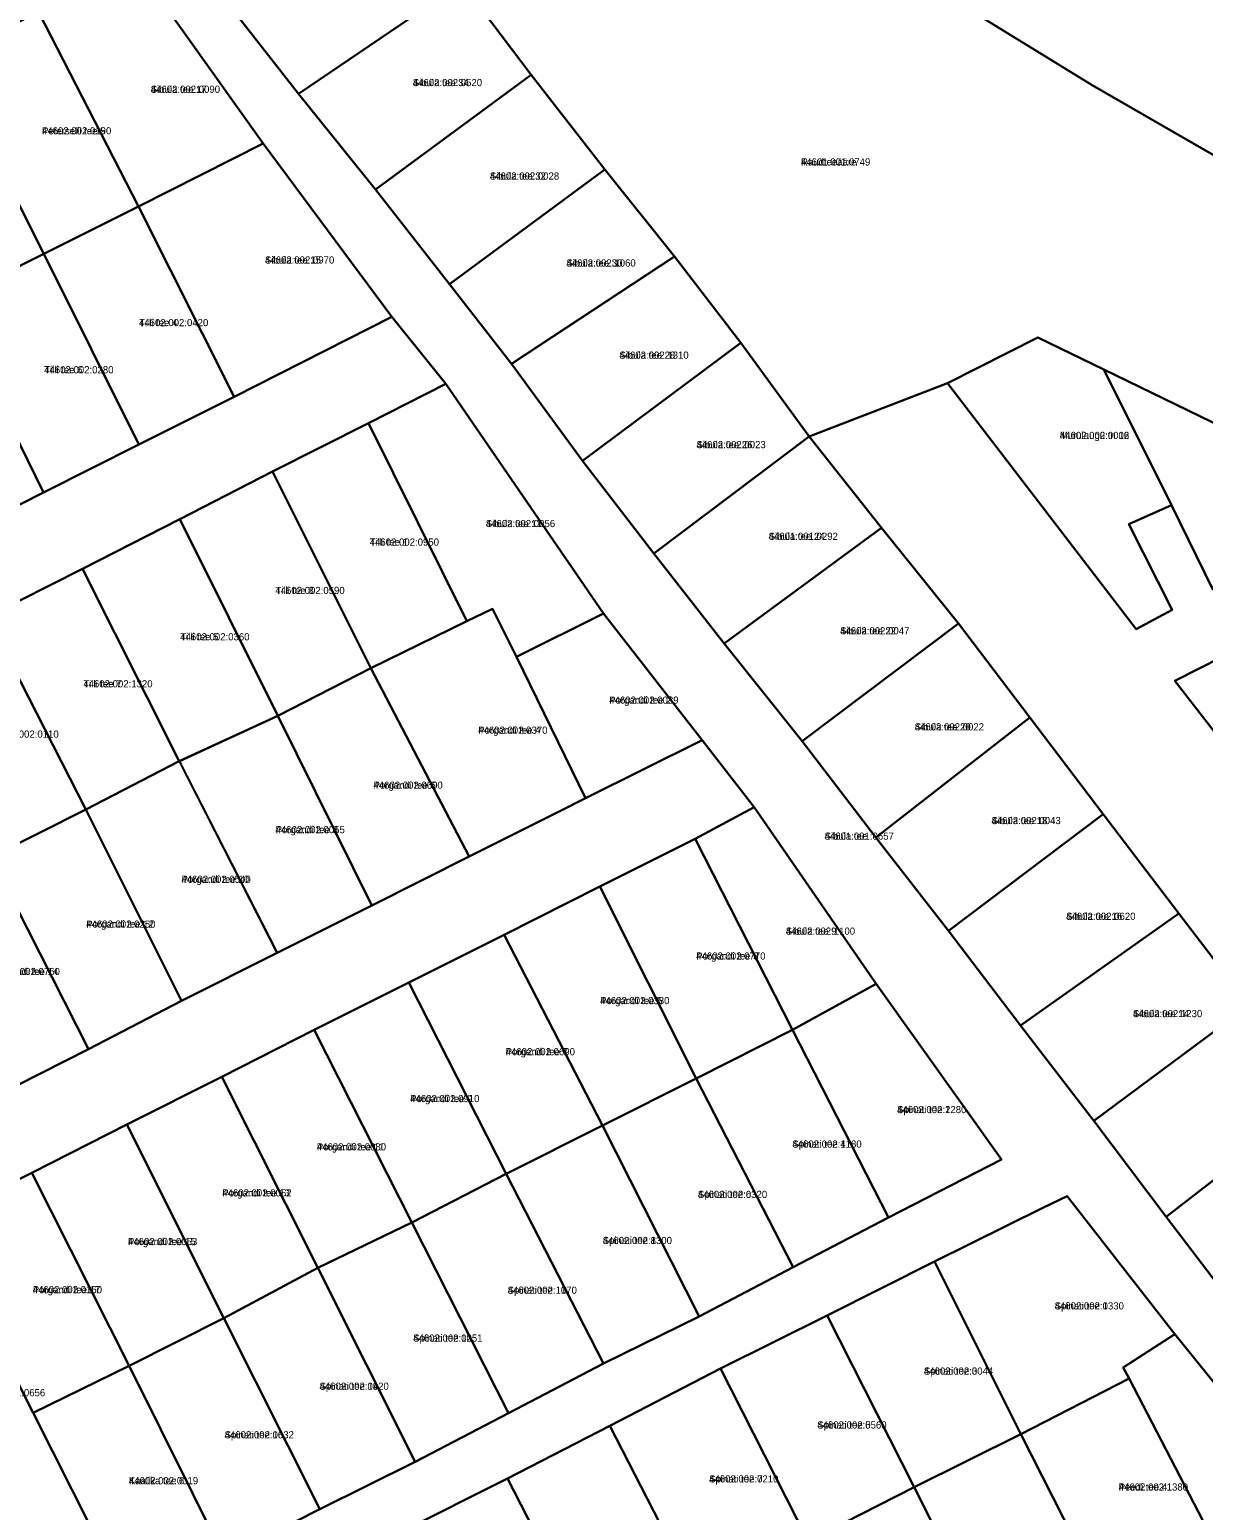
# Model space of a CAD drawing. Extents: x 551843 to 558501, y 6589003 to 6595718.
# Drawn here: x 554896.4 to 555142, y 6592596.3 to 6592906.2 of the extents above; entities that cross this region are included whole.
import ezdxf

# ---------------------------------------------------------------- set-up
doc = ezdxf.new("R2010")
doc.units = 0
for name, color, linetype in [('L_AADRESS', 7, 'Continuous'), ('PIIR', 7, 'Continuous'), ('TUNNUS', 7, 'Continuous')]:
    doc.layers.add(name, color=color, linetype=linetype)

msp = doc.modelspace()

# ---------------------------------------------------------------- linework, layer by layer
at = {"layer": 'PIIR'}
for points in [[(555357.71, 6592732.06), (555331.9, 6592760.71), (555302.6, 6592785.47), (555269.03, 6592807.67), (555235.4, 6592827.33), (555118.69, 6592894.62), (555044.93, 6592939.98), (555015.71, 6592961.33), (554988.11, 6592984.79), (554962.01, 6593010.23), (554937.73, 6593037.35), (554915.67, 6593065.87), (554895.44, 6593095.83), (554875.06, 6593131.38), (554857.59, 6593168.3), (554843.07, 6593206.48), (554831.62, 6593245.96)], [(554831.62, 6593245.96), (554843.07, 6593206.48), (554857.59, 6593168.3), (554875.06, 6593131.38), (554895.44, 6593095.83), (554915.67, 6593065.87), (554937.73, 6593037.35), (554962.01, 6593010.23), (554988.11, 6592984.79), (555015.71, 6592961.33), (555044.93, 6592939.98), (555118.69, 6592894.62), (555235.4, 6592827.33), (555269.03, 6592807.67), (555302.6, 6592785.47), (555331.9, 6592760.71), (555357.71, 6592732.06)], [(554937.17, 6592586.43), (554957.1, 6592596.52), (554977.01, 6592606.45), (554996.59, 6592616.65), (555016.42, 6592627.02), (555036.46, 6592636.84), (555056.16, 6592647.21), (555076.11, 6592657.57), (555099.74, 6592669.68), (555073.53, 6592706.46), (555047.96, 6592743.47), (555037.07, 6592757.5), (555016.41, 6592784.02), (554983.42, 6592832.06), (554972.12, 6592846.08), (554945.2, 6592882.4), (554918.38, 6592920.14)], [(555379.25, 6592709.61), (555333.63, 6592731.77), (555287.48, 6592754.21), (555235.64, 6592779.42), (555225.94, 6592784.13), (555194.48, 6592799.4), (555178.8, 6592807.05), (555121.11, 6592835.09), (555107.33, 6592841.78), (555088.39, 6592832.21), (555059.5, 6592821.07), (555045.19, 6592840.66), (555031.29, 6592858.7), (555016.73, 6592876.96), (555001.32, 6592896.74), (554986.83, 6592915.99)], [(554938.02, 6592911.42), (554952.61, 6592892.79), (554968.73, 6592872.78), (554984.2, 6592852.9), (554997.2, 6592836.28), (555012.03, 6592815.96), (555026.99, 6592796.53), (555041.71, 6592777.75), (555057.98, 6592757.31), (555073.44, 6592737.12), (555088.6, 6592717.61), (555103.7, 6592697.74), (555119.02, 6592677.8), (555134.21, 6592657.71), (555149.2, 6592638.05)], [(554879.63, 6592799.39), (554899.28, 6592809.31), (554919.22, 6592819.36), (554939.16, 6592829.38), (554972.12, 6592846.08), (554983.42, 6592832.06), (554967.24, 6592823.87), (554947.19, 6592813.73), (554927.78, 6592803.74), (554907.45, 6592793.36), (554887.5, 6592783.3)], [(555151.56, 6592701.94), (555136.8, 6592721.21), (555120.98, 6592742), (555105.63, 6592762.22), (555090.71, 6592781.94), (555074.62, 6592801.95), (555059.5, 6592821.07), (555088.39, 6592832.21), (555127.87, 6592780.7), (555135.46, 6592784.75), (555126.36, 6592802.68), (555135.28, 6592806.7), (555143.94, 6592789.01)], [(555171.08, 6592787.67), (555135.97, 6592769.94), (555153.13, 6592747.81)], [(554888.68, 6592682.72), (554908.65, 6592692.84), (554928.17, 6592702.94), (554948.16, 6592712.97), (554967.96, 6592722.91), (554988.33, 6592733.16), (555007.3, 6592742.64), (555012.67, 6592745.32), (555037.07, 6592757.5), (555047.96, 6592743.47), (555035.64, 6592736.84), (555015.66, 6592726.88), (554995.66, 6592716.72), (554975.72, 6592706.75), (554955.9, 6592696.86), (554936.57, 6592686.99), (554916.68, 6592677.03), (554896.85, 6592666.95), (554876.81, 6592656.9), (554897.07, 6592616.68), (554917.4, 6592576.46)], [(555162.2, 6592600.73), (555136.01, 6592633.16), (555113.48, 6592662.05), (555108.35, 6592659.6), (555085.68, 6592648.33), (555063.22, 6592637.04), (555040.93, 6592625.99), (555017.79, 6592613.99), (554996.34, 6592602.97), (554973.97, 6592591.72)]]:
    msp.add_lwpolyline(points, dxfattribs=at)
for points in [[(554952.61, 6592892.79), (554938.02, 6592911.42), (554971.51, 6592936.51), (554986.83, 6592915.99)], [(554919.11, 6592869.18), (554898.19, 6592909.95), (554918.38, 6592920.14), (554945.2, 6592882.4)], [(554968.73, 6592872.78), (554952.61, 6592892.79), (554986.83, 6592915.99), (555001.32, 6592896.74)], [(554899.34, 6592859.3), (554878.78, 6592900.13), (554898.19, 6592909.95), (554919.11, 6592869.18)], [(554858.94, 6592890.16), (554878.78, 6592900.13), (554899.34, 6592859.3), (554879.57, 6592849.36)], [(554968.73, 6592872.78), (555001.32, 6592896.74), (555016.73, 6592876.96), (554984.2, 6592852.9)], [(554945.2, 6592882.4), (554972.12, 6592846.08), (554939.16, 6592829.38), (554919.11, 6592869.18)], [(554997.2, 6592836.28), (554984.2, 6592852.9), (555016.73, 6592876.96), (555031.29, 6592858.7)], [(554919.11, 6592869.18), (554939.16, 6592829.38), (554919.22, 6592819.36), (554899.34, 6592859.3)], [(554879.59, 6592849.37), (554899.34, 6592859.3), (554919.22, 6592819.36), (554899.28, 6592809.31)], [(555012.03, 6592815.96), (554997.2, 6592836.28), (555031.29, 6592858.7), (555045.19, 6592840.66)], [(554879.59, 6592849.37), (554899.28, 6592809.31), (554879.63, 6592799.39), (554858.83, 6592839.26)], [(555045.19, 6592840.66), (555059.5, 6592821.07), (555026.99, 6592796.53), (555012.03, 6592815.96)], [(555088.39, 6592832.21), (555107.33, 6592841.78), (555121.11, 6592835.09), (555135.28, 6592806.7), (555126.36, 6592802.68), (555135.46, 6592784.75), (555127.87, 6592780.7)], [(555178.8, 6592807.05), (555143.94, 6592789.01), (555135.28, 6592806.7), (555121.11, 6592835.09)], [(554967.24, 6592823.87), (554983.42, 6592832.06), (555016.41, 6592784.02), (554998.21, 6592774.93), (554993.21, 6592785), (554987.84, 6592782.4)], [(554967.24, 6592823.87), (554987.84, 6592782.4), (554967.78, 6592772.56), (554947.19, 6592813.73)], [(555041.71, 6592777.75), (555026.99, 6592796.53), (555059.5, 6592821.07), (555074.62, 6592801.95)], [(554947.19, 6592813.73), (554967.78, 6592772.56), (554948.28, 6592762.6), (554927.78, 6592803.74)], [(554927.78, 6592803.74), (554948.28, 6592762.6), (554927.67, 6592753.11), (554907.45, 6592793.36)], [(555041.71, 6592777.75), (555074.62, 6592801.95), (555090.71, 6592781.94), (555057.98, 6592757.31)], [(554907.45, 6592793.36), (554927.67, 6592753.11), (554908.09, 6592742.97), (554887.5, 6592783.3)], [(554967.78, 6592772.56), (554987.84, 6592782.4), (554993.21, 6592785), (554998.21, 6592774.93), (555012.67, 6592745.32), (555007.3, 6592742.64), (554988.33, 6592733.16)], [(555178.6, 6592760.83), (555153.13, 6592747.81), (555135.97, 6592769.94), (555171.08, 6592787.67), (555183.36, 6592763.27)], [(554867.79, 6592773.85), (554887.5, 6592783.3), (554908.09, 6592742.97), (554888.23, 6592733)], [(554998.21, 6592774.93), (555016.41, 6592784.02), (555037.07, 6592757.5), (555012.67, 6592745.32)], [(555090.71, 6592781.94), (555105.63, 6592762.22), (555073.44, 6592737.12), (555057.98, 6592757.31)], [(554967.78, 6592772.56), (554988.33, 6592733.16), (554967.96, 6592722.91), (554948.28, 6592762.6)], [(554927.69, 6592753.12), (554948.28, 6592762.6), (554967.96, 6592722.91), (554948.16, 6592712.97)], [(555105.63, 6592762.22), (555120.98, 6592742), (555088.6, 6592717.61), (555073.44, 6592737.12)], [(554927.67, 6592753.11), (554948.16, 6592712.97), (554928.17, 6592702.94), (554908.09, 6592742.97)], [(554908.09, 6592742.97), (554928.17, 6592702.94), (554908.65, 6592692.84), (554888.23, 6592733)], [(555056.02, 6592696.84), (555035.64, 6592736.84), (555047.96, 6592743.47), (555073.53, 6592706.46)], [(555103.7, 6592697.74), (555088.6, 6592717.61), (555120.98, 6592742), (555136.8, 6592721.21)], [(555035.82, 6592686.67), (555015.66, 6592726.88), (555035.64, 6592736.84), (555056.02, 6592696.84)], [(554888.23, 6592733), (554908.65, 6592692.84), (554888.68, 6592682.72), (554867.74, 6592723.07)], [(555015.66, 6592726.88), (555035.82, 6592686.67), (555016.22, 6592676.81), (554995.66, 6592716.72)], [(555119.02, 6592677.8), (555103.7, 6592697.74), (555136.8, 6592721.21), (555151.56, 6592701.94)], [(554995.66, 6592716.72), (555016.22, 6592676.81), (554996.07, 6592666.74), (554975.72, 6592706.75)], [(554975.72, 6592706.75), (554996.07, 6592666.74), (554976.33, 6592656.54), (554955.9, 6592696.86)], [(555076.11, 6592657.57), (555056.02, 6592696.84), (555073.53, 6592706.46), (555099.74, 6592669.68)], [(555134.21, 6592657.71), (555119.02, 6592677.8), (555151.56, 6592701.94), (555166.31, 6592682.62)], [(554955.9, 6592696.86), (554976.33, 6592656.54), (554956.66, 6592647.03), (554936.57, 6592686.99)], [(555056.16, 6592647.21), (555035.82, 6592686.67), (555056.02, 6592696.84), (555076.11, 6592657.57)], [(554916.68, 6592677.03), (554936.57, 6592686.99), (554956.66, 6592647.03), (554937.02, 6592636.48)], [(555035.82, 6592686.67), (555056.16, 6592647.21), (555036.46, 6592636.84), (555016.22, 6592676.81)], [(555149.2, 6592638.05), (555134.21, 6592657.71), (555166.31, 6592682.62), (555181.58, 6592662.64)], [(554896.85, 6592666.95), (554916.68, 6592677.03), (554937.02, 6592636.48), (554917.21, 6592626.51)], [(555016.22, 6592676.81), (555036.46, 6592636.84), (555016.42, 6592627.02), (554996.07, 6592666.74)], [(554896.85, 6592666.95), (554917.21, 6592626.51), (554897.07, 6592616.68), (554876.81, 6592656.9)], [(554996.07, 6592666.74), (555016.42, 6592627.02), (554996.59, 6592616.65), (554976.33, 6592656.54)], [(555103.76, 6592612.25), (555085.68, 6592648.33), (555108.35, 6592659.6), (555113.48, 6592662.05), (555136.01, 6592633.16), (555125.2, 6592626.2), (555126.42, 6592623.85)], [(554956.66, 6592647.03), (554976.33, 6592656.54), (554996.59, 6592616.65), (554977.01, 6592606.45)], [(554956.66, 6592647.03), (554977.01, 6592606.45), (554957.1, 6592596.52), (554937.02, 6592636.48)], [(555063.22, 6592637.04), (555085.68, 6592648.33), (555103.76, 6592612.25), (555081.44, 6592601.11)], [(554937.02, 6592636.48), (554957.1, 6592596.52), (554937.17, 6592586.43), (554917.21, 6592626.51)], [(555059.3, 6592589.8), (555040.93, 6592625.99), (555063.22, 6592637.04), (555081.44, 6592601.11)], [(555126.42, 6592623.85), (555125.2, 6592626.2), (555136.01, 6592633.16), (555162.2, 6592600.73), (555163.99, 6592598.07), (555144.75, 6592588.48)], [(554917.21, 6592626.51), (554937.17, 6592586.43), (554917.4, 6592576.46), (554897.07, 6592616.68)], [(555036.09, 6592578.25), (555017.79, 6592613.99), (555040.93, 6592625.99), (555059.3, 6592589.8)], [(555121.73, 6592576.8), (555103.76, 6592612.25), (555126.42, 6592623.85), (555144.75, 6592588.48)], [(554996.34, 6592602.97), (555017.79, 6592613.99), (555036.09, 6592578.25), (555014.65, 6592567.27)], [(555099.41, 6592565.48), (555081.44, 6592601.11), (555103.76, 6592612.25), (555121.73, 6592576.8)], [(554996.34, 6592602.97), (555014.65, 6592567.27), (554991.94, 6592555.95), (554973.97, 6592591.72)], [(555077.06, 6592554.16), (555059.3, 6592589.8), (555081.44, 6592601.11), (555099.41, 6592565.48)]]:
    msp.add_lwpolyline(points, close=True, dxfattribs=at)

# ---------------------------------------------------------------- texts
at = {"layer": 'L_AADRESS'}
for s, p in [('Sibula tee 17', (554921.7, 6592892.98)), ('Sibula tee 34', (554976.54, 6592894.38)), ('Peterselli tee 5', (554898.95, 6592884.28)), ('Raudteeääre', (555057.77, 6592877.77)), ('Sibula tee 32', (554992.67, 6592874.82)), ('Sibula tee 15', (554945.61, 6592857.25)), ('Sibula tee 30', (555008.68, 6592856.62)), ('Tilli tee 4', (554919.25, 6592844.14)), ('Sibula tee 28', (555019.76, 6592837.33)), ('Tilli tee 6', (554899.41, 6592834.27)), ('Murulaugu tn 16', (555111.93, 6592820.53)), ('Sibula tee 26', (555035.89, 6592818.6)), ('Sibula tee 11', (554991.82, 6592802.08)), ('Sibula tee 24', (555050.99, 6592799.41)), ('Tilli tee 1', (554967.52, 6592798.2)), ('Tilli tee 3', (554947.78, 6592788.08)), ('Tilli tee 5', (554927.87, 6592778.38)), ('Sibula tee 22', (555065.95, 6592779.63)), ('Tilli tee 7', (554907.59, 6592768.53)), ('Porgandi tee 2', (555017.64, 6592765.12)), ('Porgandi tee 4', (554990.23, 6592758.83)), ('Sibula tee 20', (555081.56, 6592759.53)), ('Porgandi tee 6', (554968.3, 6592747.32)), ('Sibula tee 18', (555097.62, 6592739.91)), ('Porgandi tee 8', (554947.82, 6592738.01)), ('Sibula tee', (555062.7, 6592736.65)), ('Porgandi tee 10', (554928.12, 6592727.62)), ('Porgandi tee 12', (554908.2, 6592718.24)), ('Sibula tee 16', (555113.26, 6592719.87)), ('Sibula tee 9', (555054.59, 6592716.77)), ('Porgandi tee 3', (555035.84, 6592711.56)), ('Porgandi tee 14', (554888.2, 6592708.32)), ('Porgandi tee 5', (555015.74, 6592702.23)), ('Sibula tee 14', (555127.23, 6592699.51)), ('Porgandi tee 7', (554995.97, 6592691.53)), ('Porgandi tee 9', (554975.98, 6592681.72)), ('Spinati tee 2', (555077.88, 6592679.42)), ('Porgandi tee 11', (554956.45, 6592671.61)), ('Spinati tee 4', (555055.96, 6592672.2)), ('Porgandi tee 13', (554936.67, 6592661.98)), ('Spinati tee 6', (555036.19, 6592661.66)), ('Porgandi tee 15', (554916.94, 6592651.79)), ('Spinati tee 8', (555016.27, 6592652.02)), ('Porgandi tee 17', (554897.01, 6592641.72)), ('Spinati tee 10', (554996.38, 6592641.61)), ('Spinati tee 1', (555110.84, 6592638.33)), ('Spinati tee 12', (554976.62, 6592631.59)), ('Spinati tee 3', (555083.49, 6592624.68)), ('Spinati tee 14', (554957.02, 6592621.51)), ('Spinati tee 5', (555061.18, 6592613.4)), ('Spinati tee 16', (554937.16, 6592611.34)), ('Kaalika tee 6', (554917.12, 6592601.74)), ('Spinati tee 7', (555038.54, 6592602.11)), ('Peedi tee 4', (555124.25, 6592600.41))]:
    msp.add_text(s, height=1.5, dxfattribs=at).set_placement(p)
at = {"layer": 'TUNNUS'}
for s, p in [('44602:002:0090', (554921.7, 6592892.98)), ('44602:002:0520', (554976.54, 6592894.38)), ('44602:002:0190', (554898.95, 6592884.28)), ('44601:001:0749', (555057.77, 6592877.77)), ('44602:002:0028', (554992.67, 6592874.82)), ('44602:002:0970', (554945.61, 6592857.25)), ('44602:002:1060', (555008.68, 6592856.62)), ('44602:002:0420', (554919.25, 6592844.14)), ('44602:002:1310', (555019.76, 6592837.33)), ('44602:002:0280', (554899.41, 6592834.27)), ('44602:002:0002', (555111.93, 6592820.53)), ('44602:002:0023', (555035.89, 6592818.6)), ('44602:002:0056', (554991.82, 6592802.08)), ('44601:001:0292', (555050.99, 6592799.41)), ('44602:002:0950', (554967.52, 6592798.2)), ('44602:002:0590', (554947.78, 6592788.08)), ('44602:002:0360', (554927.87, 6592778.38)), ('44602:002:0047', (555065.95, 6592779.63)), ('44602:002:1320', (554907.59, 6592768.53)), ('44602:002:0039', (555017.64, 6592765.12)), ('44602:002:0370', (554990.23, 6592758.83)), ('44602:002:0022', (555081.56, 6592759.53)), ('44602:002:0110', (554887.94, 6592758.01)), ('44602:002:0600', (554968.3, 6592747.32)), ('44602:002:0043', (555097.62, 6592739.91)), ('44602:002:0055', (554947.82, 6592738.01)), ('44601:001:0657', (555062.7, 6592736.65)), ('44602:002:0540', (554928.12, 6592727.62)), ('44602:002:0250', (554908.2, 6592718.24)), ('44602:002:0620', (555113.26, 6592719.87)), ('44602:002:1100', (555054.59, 6592716.77)), ('44602:002:0770', (555035.84, 6592711.56)), ('44602:002:0760', (554888.2, 6592708.32)), ('44602:002:0380', (555015.74, 6592702.23)), ('44602:002:1230', (555127.23, 6592699.51)), ('44602:002:0690', (554995.97, 6592691.53)), ('44602:002:0910', (554975.98, 6592681.72)), ('44602:002:1280', (555077.88, 6592679.42)), ('44602:002:1180', (555055.96, 6592672.2)), ('44602:002:0080', (554956.45, 6592671.61)), ('44602:002:0052', (554936.67, 6592661.98)), ('44602:002:0320', (555036.19, 6592661.66)), ('44602:002:0053', (554916.94, 6592651.79)), ('44602:002:1300', (555016.27, 6592652.02)), ('44602:002:0160', (554897.01, 6592641.72)), ('44602:002:1170', (554996.38, 6592641.61)), ('44602:002:0330', (555110.84, 6592638.33)), ('44602:002:0051', (554976.62, 6592631.59)), ('44602:002:0044', (555083.49, 6592624.68)), ('44601:001:0656', (554885.12, 6592620.16)), ('44602:002:0920', (554957.02, 6592621.51)), ('44602:002:0560', (555061.18, 6592613.4)), ('44602:002:0032', (554937.16, 6592611.34)), ('44602:002:0019', (554917.12, 6592601.74)), ('44602:002:0210', (555038.54, 6592602.11)), ('44602:002:1380', (555124.25, 6592600.41))]:
    msp.add_text(s, height=1.5, dxfattribs=at).set_placement(p)

doc.saveas('drawing.dxf')
